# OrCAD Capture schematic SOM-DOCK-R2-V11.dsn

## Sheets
1 Title / Notes: title: SOMPLC-DOCKV1 R2; rev: 0.8; company: TI
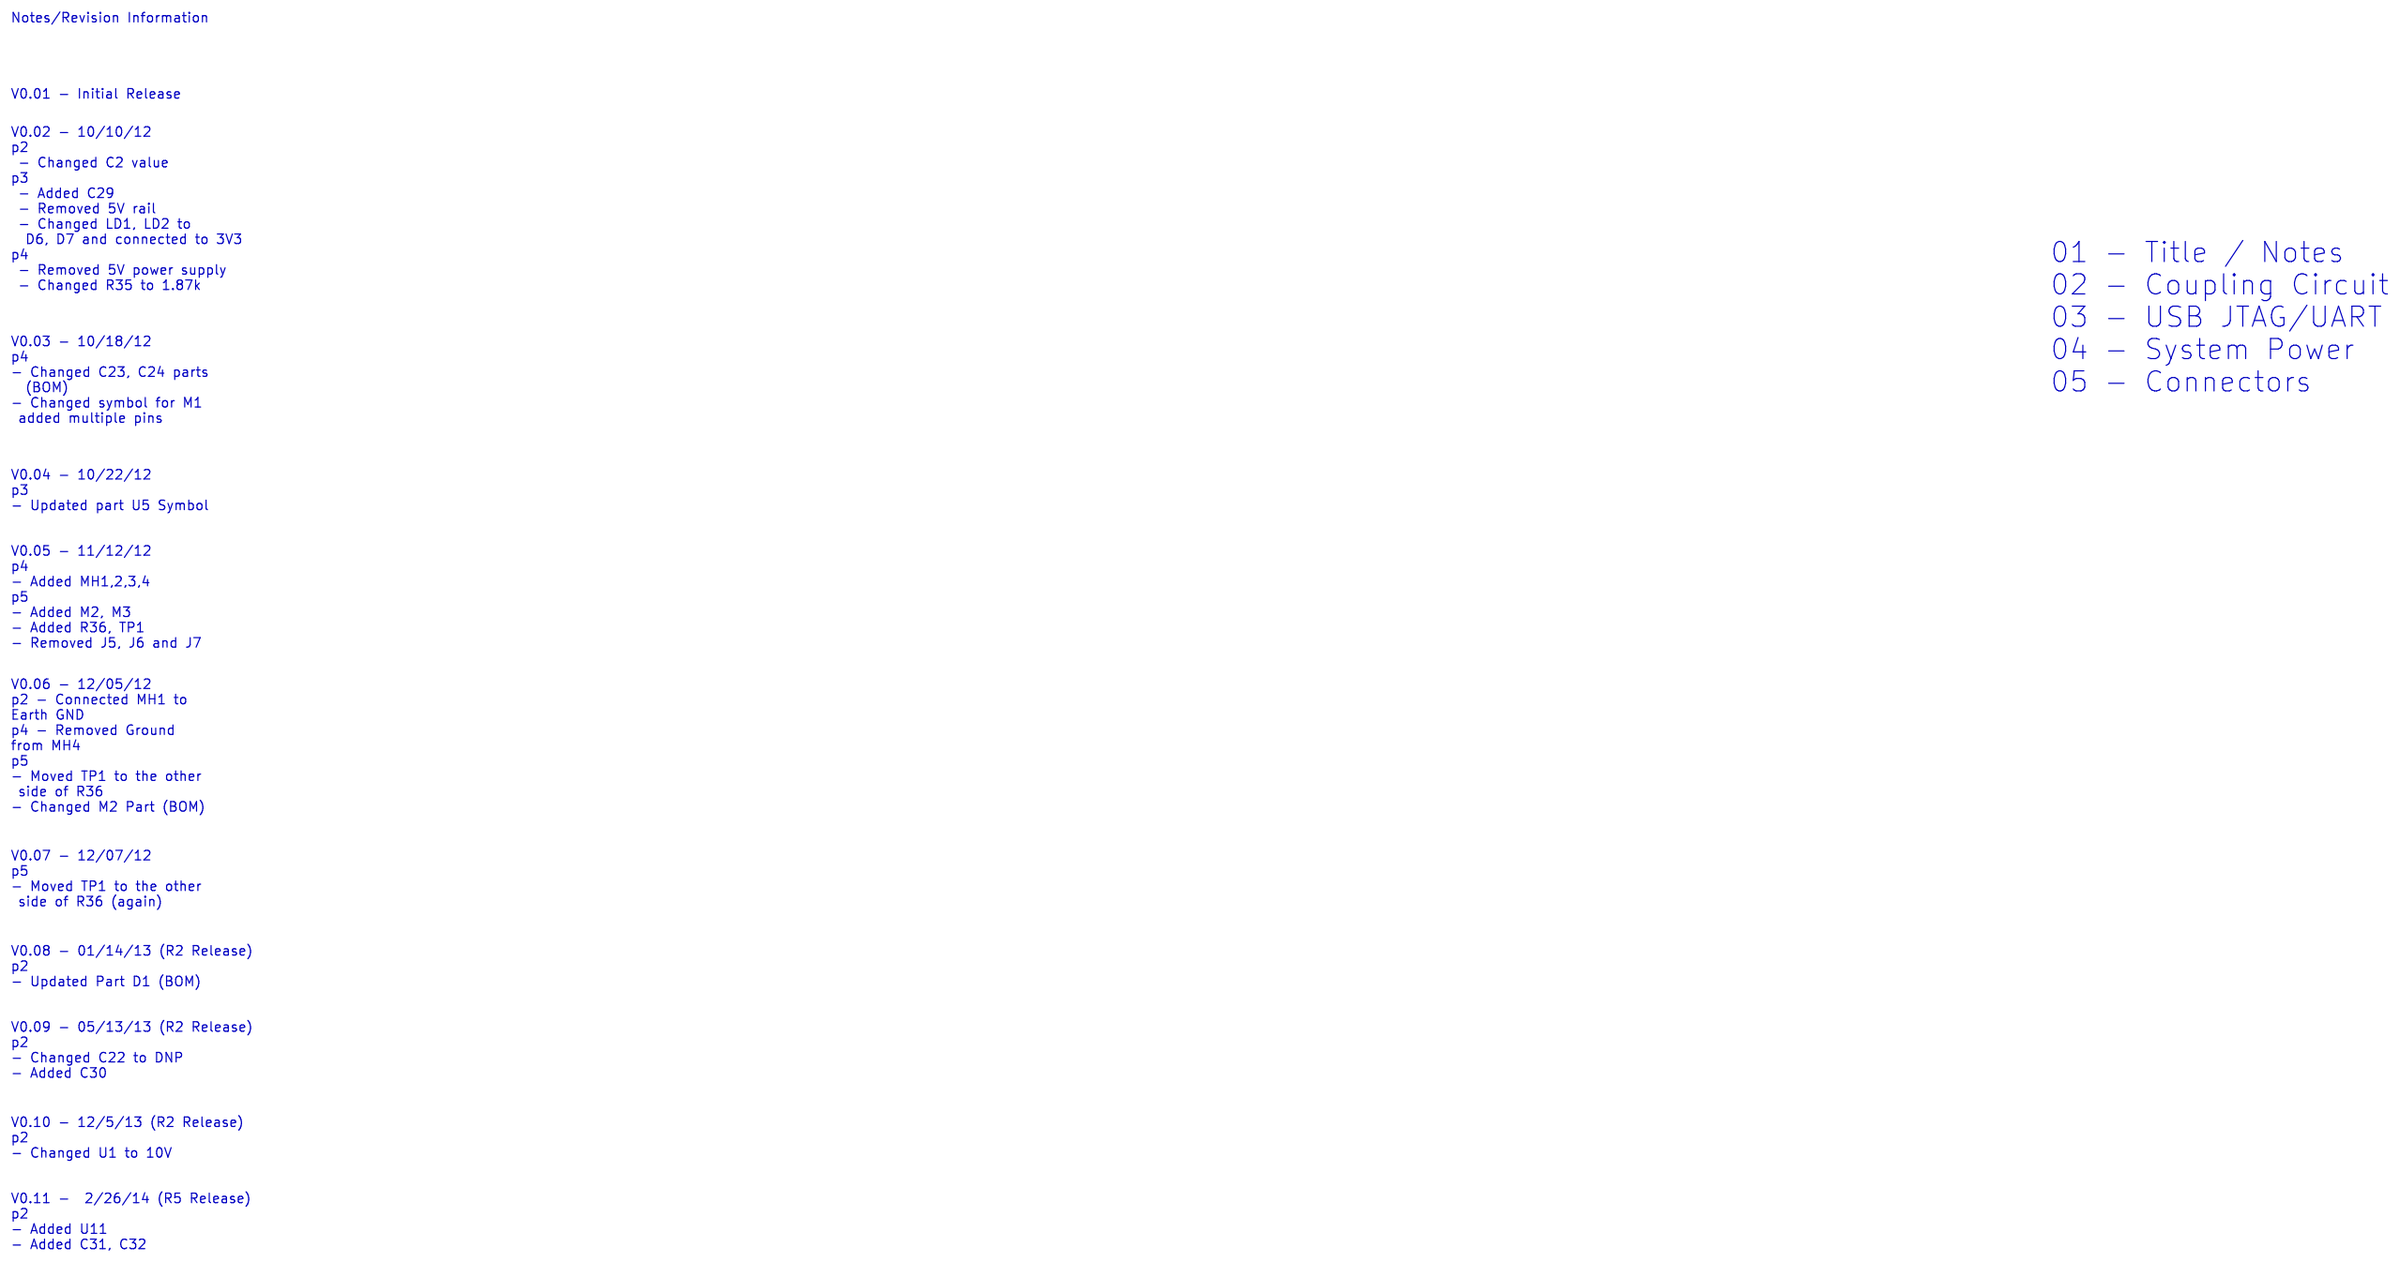
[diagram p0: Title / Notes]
2 Coupling Circuit: size B
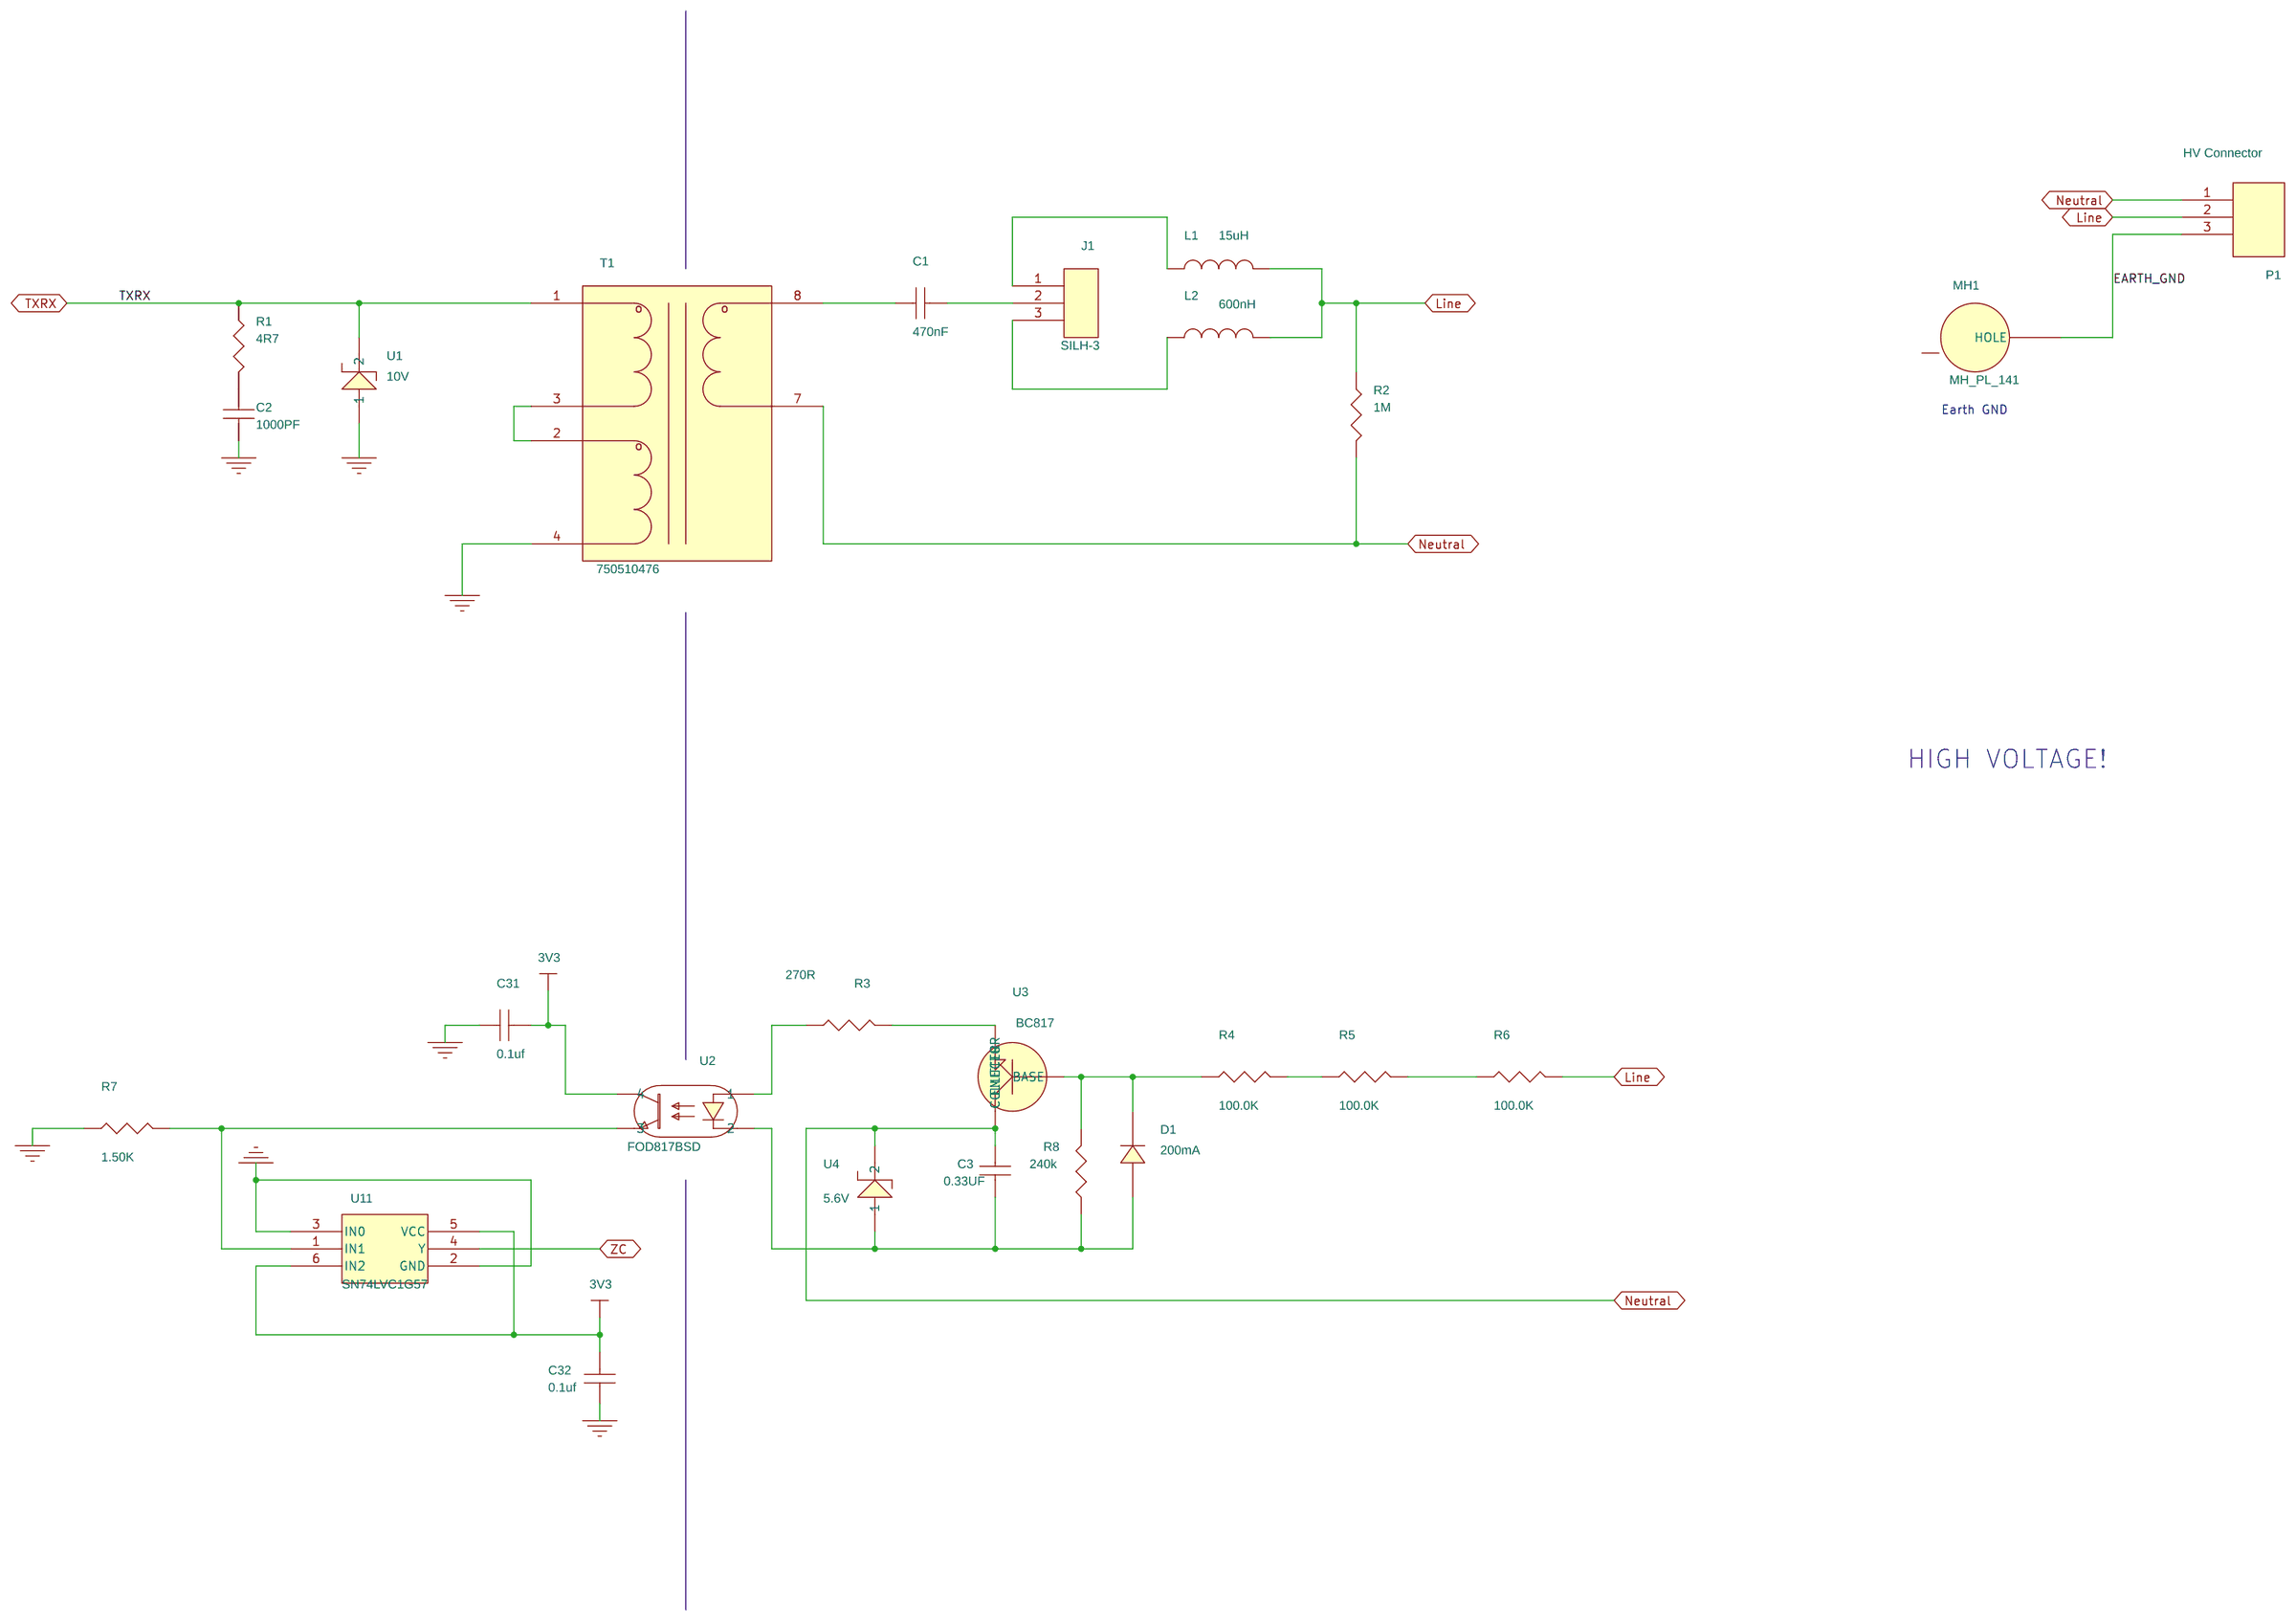
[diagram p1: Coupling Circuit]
3 USB JTAG/UART: size B
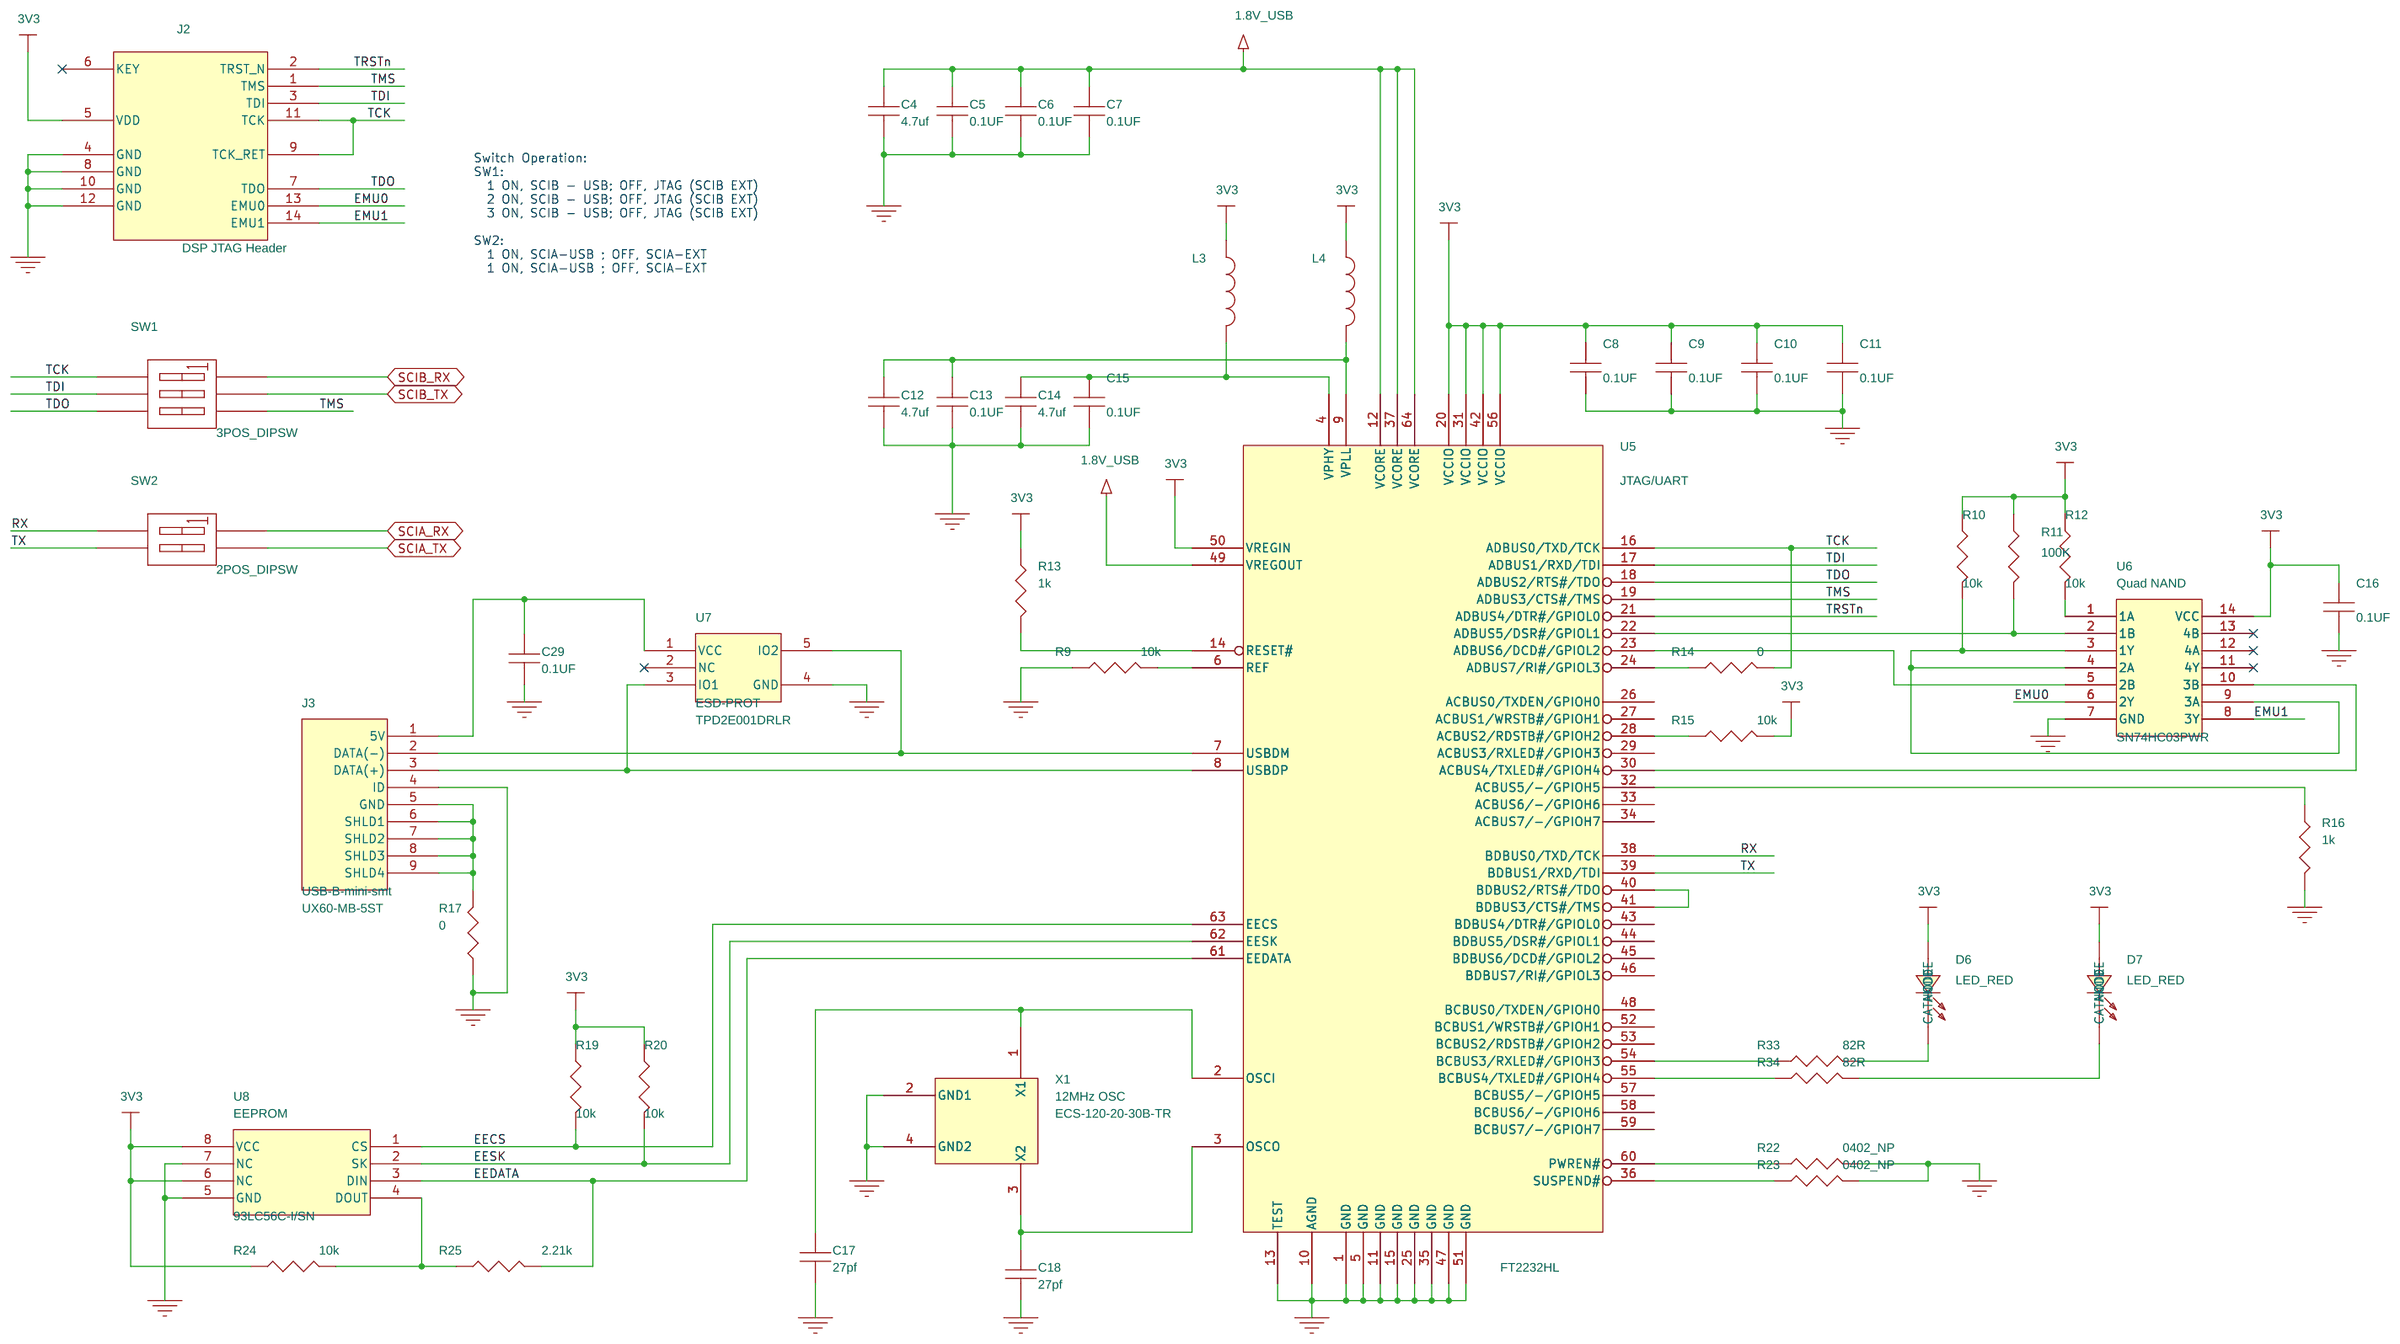
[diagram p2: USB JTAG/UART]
4 System Power: size B
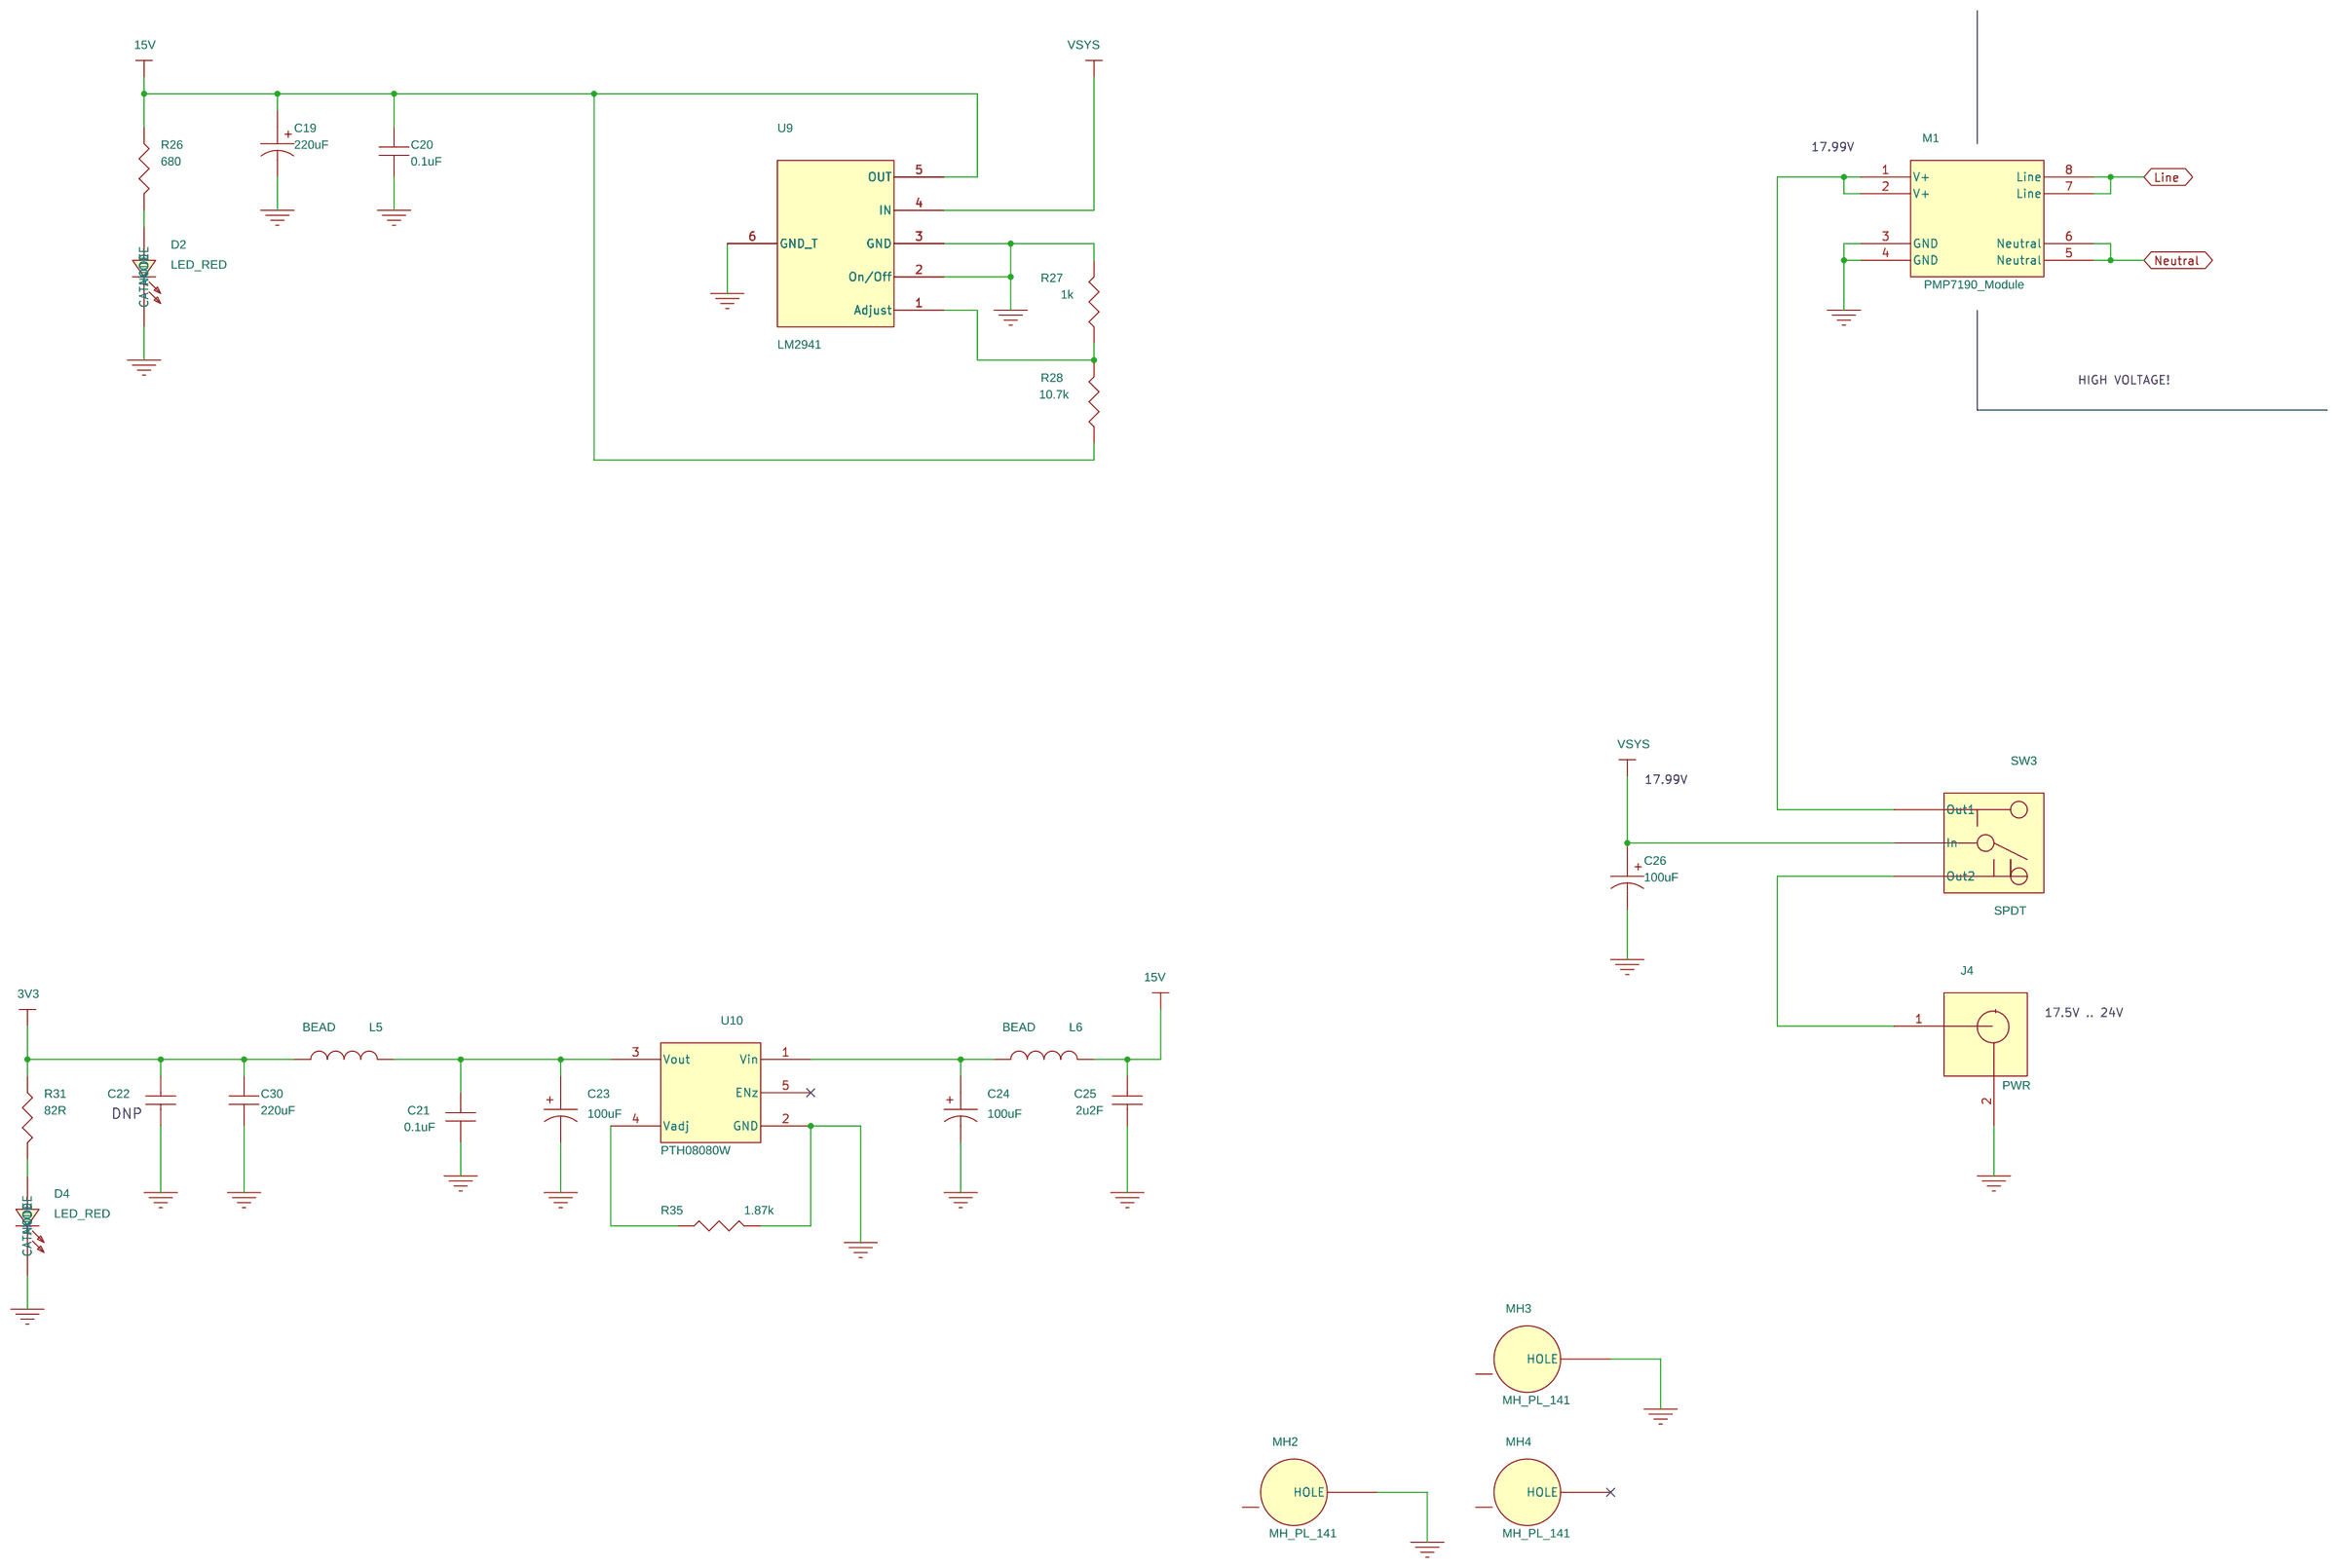
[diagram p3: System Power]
5 Connectors: size B
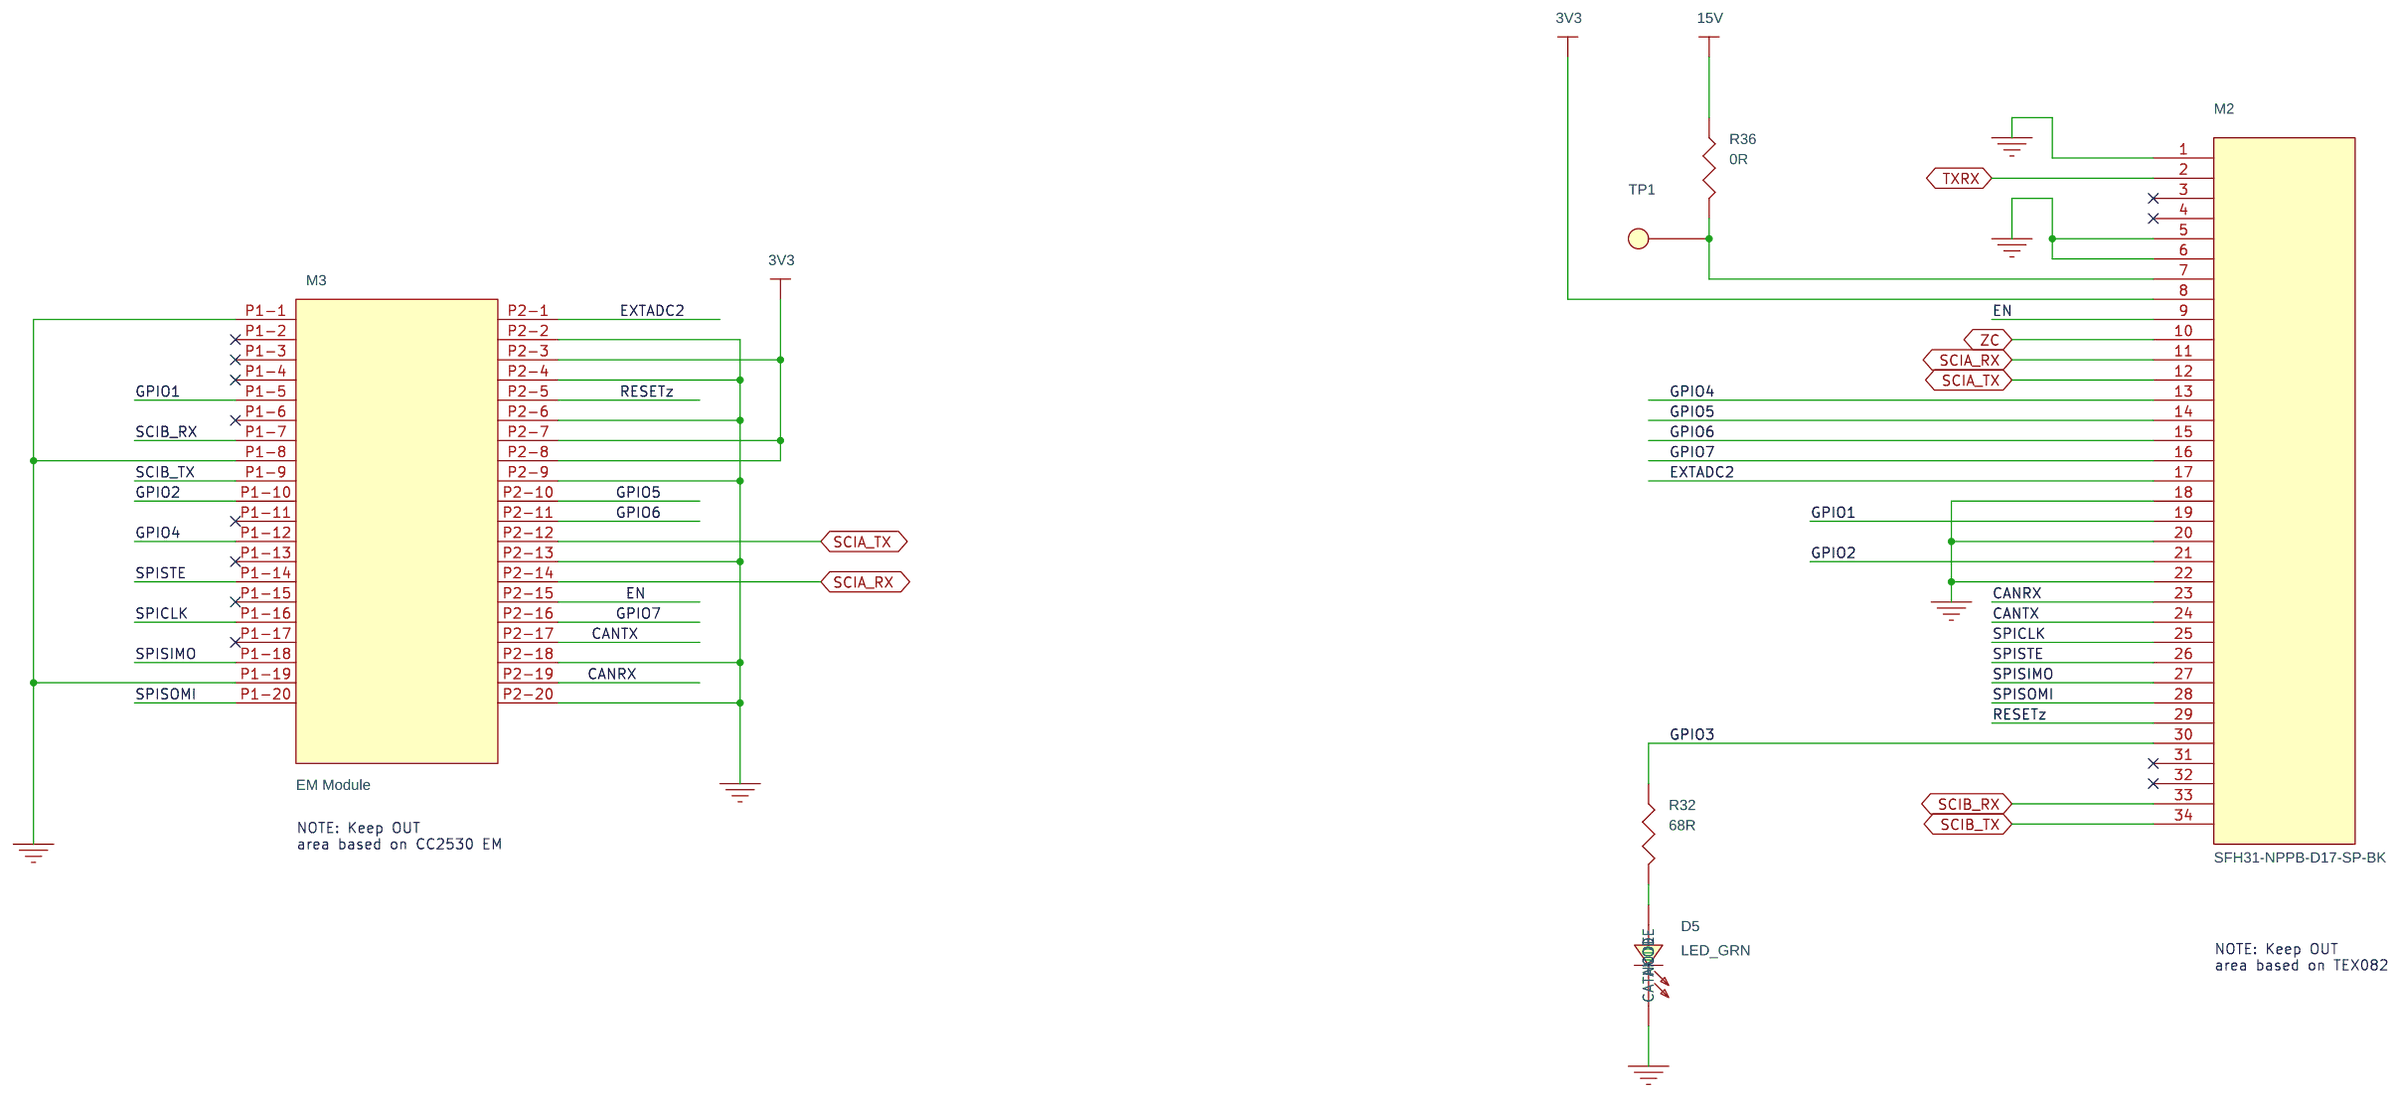
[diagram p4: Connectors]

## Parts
sheet Connectors
D5  LED_GRN  [LED0805]
M2  SFH31-NPPB-D17-SP-BK  [Female]
M3  EM Module  [Male]
R32  68R  [R0402]
R36  0R  [R0805]
TP1  TP_60  [TP_60]
sheet Coupling Circuit
C1  470nF  [Axial 0.591" (15.00mm) Spacing]
C2  1000PF  [C0603]
C3  0.33UF  [C0603]
C31  0.1uf  [C0805]
C32  0.1uf  [C0805]
D1  200mA  [LL-34]
J1  SILH-3  [HDR_1x3_100MILL_THRU_HOLE]
L1  15uH  [DR1040]
L2  600nH  [0.571" L x 0.492" W x 0.197" H]
MH1  MH_PL_141  [MH_141]
P1  HV Connector  [see datasheet]
R1  4R7  [R0805]
R2  1M  [R0805]
R3  270R  [R0805]
R4  100.0K  [R0805]
R5  100.0K  [R0805]
R6  100.0K  [R0805]
R7  1.50K  [R0805]
R8  240k  [R0805]
T1  750510476  [see datasheet]
U1  10V  [DO-214AA]
U2  FOD817BSD  [4-SMD]
U3  BC817  [SOT-23-3]
U4  5.6V  [LL-34]
U11  SN74LVC1G57  [SOT-23-6 (DVB)]
sheet System Power
C19  220uF  [Radial]
C20  0.1uF  [C0603]
C21  0.1uF  [C0603]
C22  2u2F  [C1210]
C23  100uF  [C2917P]
C24  100uF  [C2917P]
C25  2u2F  [C1210]
C26  100uF  [Radial]
C30  220uF  [C1210]
D2  LED_RED  [LED0805]
D4  LED_RED  [LED0805]
J4  PWR  [thru-hole]
L5  BEAD  [IND0402]
L6  BEAD  [IND0402]
M1  PMP7190_Module  [custom]
MH2  MH_PL_141  [MH_141]
MH3  MH_PL_141  [MH_141]
MH4  MH_PL_141  [MH_141]
R26  680  [R0402]
R27  1k  [R0402]
R28  10.7k  [R0402]
R31  82R  [R0402]
R35  1.87k  [R0402]
SW3  SPDT  [2 thru-hole]
U9  LM2941  [TO-263-5]
U10  PTH08080W  [PTH_5]
sheet USB JTAG/UART
C4  4.7uf  [C0402]
C5  0.1UF  [C0402]
C6  0.1UF  [C0402]
C7  0.1UF  [C0402]
C8  0.1UF  [C0402]
C9  0.1UF  [C0402]
C10  0.1UF  [C0402]
C11  0.1UF  [C0402]
C12  4.7uf  [C0402]
C13  0.1UF  [C0402]
C14  4.7uf  [C0402]
C15  0.1UF  [C0402]
C16  0.1UF  [C0402]
C17  27pf  [C0402]
C18  27pf  [C0402]
C29  0.1UF  [C0402]
D6  LED_RED  [LED0805]
D7  LED_RED  [LED0805]
J2  DSP JTAG Header  [hdr_14p]
J3  USB-B-mini-smt  [female?]
L3  HZ0805E601R-10  [805]
L4  HZ0805E601R-10  [805]
R9  10k  [R0402]
R10  10k  [R0402]
R11  100K  [R0603]
R12  10k  [R0402]
R13  1k  [R0402]
R14  0  [R0402]
R15  10k  [R0402]
R16  1k  [R0402]
R17  0  [R0402]
R19  10k  [R0402]
R20  10k  [R0402]
R22  0402_NP  [R0402]
R23  0402_NP  [R0402]
R24  10k  [R0402]
R25  2.21k  [R0402]
R33  82R  [R0402]
R34  82R  [R0402]
SW1  3POS_DIPSW  [3PDIPSW]
SW2  2POS_DIPSW  [2PDIPSW]
U5  JTAG/UART  [64-LQFP]
U6  Quad NAND  [14-TSSOP]
U7  ESD-PROT  [SOT-553]
U8  EEPROM  [8-SOIC]
X1  12MHz OSC  [4-SMD]

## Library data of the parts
D5 = LED: LED SMD 0805 - Green; Distributor: Digikey; Distributor Part Number: 404-1021-1; Part Number: 400-00001; Part Type: FET_DIODE; Vendor: Stanley; Vendor PN: PG1112H-TR; Voltage: 2.1V
M2 = SOM34PinConnector: CONN HDR FMAL 34PS 1.27MM SMD AU; Distributor: digikey; Distributor Part Number: S9117-ND; Part Number: 320-00014; Part Type: CONN; Vendor: Sullins Connector Solutions
M3 = EM_MODULE: 2x 20P SMT HDR; Distributor: mouser; Distributor Part Number: 649-87409-110LF; Part Number: 406-00002; Part Type: Module; Vendor: FCI; Vendor PN: 87409-110LF
R32 = RES_1: RES 68 OHM 1/10W 5% 0402 SMD; Distributor: digikey; Distributor Part Number: P68JCT-ND; Part Number: 310-00139; Part Type: RES; Vendor: panasonic; Vendor PN: ERJ-2GEJ680X
R36 = RES: RES 0.0 OHM 1/8W 0805 SMD; Distributor: digikey; Distributor Part Number: 311-0.0ARCT-ND; Part Number: 310-00113; Vendor: Yageo; Vendor PN: RC0805JR-070RL
TP1 = Test_Point: 60 mil round test point, SMT; Part Number: 280-00010; Part Type: MTG_HOLE_TP; Vendor: TI; Vendor PN: TI-TP-60mil
C1 = CAP: Part Number: 300-00047; Vendor: PANASONIC; Vendor PN: ECQ-E4474KF
C2 = CAP: Capacitor,1000PF,50 V,10 %,X7R,0603; Part Number: 100-00025; Tolerance: 0.1; Vendor: AVX; Vendor PN: 06035C102KAT*A; Voltage: 50V; Datasheet: http://www.avxcorp.com/docs/Catalogs/cx7r.pdf
C3 = CAP: Part Number: 100-00126; Vendor: Murata; Vendor PN: GRM188R71C334KA01D
C31 C32 = CAP: CAP CER 0.1UF 25V 10% X7R 0805; Distributor: digikey; Distributor Part Number: 399-1168-1-ND; Part Number: 300-00131; Vendor: Kemet; Vendor PN: C0805C104K3RACTU; Voltage: 25V
D1 = DIODE_SMC: DIODE STANDARD 200mA LL-34; Distributor: Digikey; Distributor Part Number: 568-1749-1-ND; FPLIST: LL-34, LLDS, SOD80C; Part Number: 400-00010; Part Type: FET_DIODE; Vendor: NXP Semi; Vendor PN: PMLL4148L,115
J1 = CONN_1x3_100mill_STD: 3 pin 100mill standard header; Part Number: 320-00008; Part Type: CONN
L1 = INDUCTOR_AIR_CORE: INDUCTOR POWER SHIELD 15UH SMD; Distributor: Digikey; Distributor Part Number: 513-1400-1-ND; Part Number: 330-00027; Part Type: MAGNETICS; Vendor: Coiltronics/Cooper; Vendor PN: DR1040-150-R
L2 = INDUCTOR_AIR_CORE_1: COIL POWER CHOKE 600nH 27A SMD; Distributor: Digikey; Distributor Part Number: PCD2022CT-ND; Part Number: 330-00020; Part Type: MAGNETICS; Vendor: Panasonic - ECG; Vendor PN: ETQ-P5LR60XFA
MH1-MH4 = MOUNTING_HOLE_PLATE: MTG_HOLE,0.141 hole, 0.25 pad, plated; Part Number: 480-00002; Part Type: MTG_HOLE_TP; Vendor: TI; Vendor PN: 280-00002
P1 = HDR_1X3: TERM BLOCK 3POS SIDE ENT 5.08MM; Distributor: digikey; Distributor Part Number: A98343-ND; Part Number: 320-00036; Part Type: CONN; Vendor: TE Connectivity; Vendor PN: 282841-3
R1 = RES_3: Part Number: 310-00075; Part Type: RES; Vendor: Panasonic; Vendor PN: ERJ-6GEYJ4R7V
R2 = RES_7: Part Number: 110-00031; Part Type: RES; Vendor: AVX; Vendor PN: CR21-105J-*
R3 = RES_4: Part Number: 110-00238; Part Type: RES; Vendor: Rohm; Vendor PN: MCR10EZPJ271
R4 = RES_6: RESISTOR,100.0K,0.125 W,1 %,0805; Part Number: 110-00018; Part Type: RES; Tolerance: 0.01; Vendor: AVX; Vendor PN: CR21-1003F-*; Voltage: 0.125W; Datasheet: http://www.avxcorp.com/docs/Catalogs/cr-cj.pdf
R5 = RES: RESISTOR,100.0K,0.125 W,1 %,0805; Part Number: 110-00018; Tolerance: 0.01; Vendor: AVX; Vendor PN: CR21-1003F-*; Voltage: 0.125W; Datasheet: http://www.avxcorp.com/docs/Catalogs/cr-cj.pdf
R6 = RES_5: RESISTOR,100.0K,0.125 W,1 %,0805; Part Number: 110-00018; Part Type: RES; Tolerance: 0.01; Vendor: AVX; Vendor PN: CR21-1003F-*; Voltage: 0.125W; Datasheet: http://www.avxcorp.com/docs/Catalogs/cr-cj.pdf
R7 = RES_1: Part Number: 110-00048; Part Type: RES; Vendor: AVX; Vendor PN: CR21-1501F-*
R8 = RES_2: Part Number: 110-00239; Part Type: RES; Vendor: Rohm; Vendor PN: MCR10EZPF2403
T1 = XFMR_PLC_2: Transformer PLC; Part Number: 330-00033; Part Type: MAGNETICS; Vendor: WURTH ELEKTRONIK
U1 = Diode_Zener: TRANSIL 600W 10V BIDIR SMB; Distributor: digikey; Distributor Part Number: 497-7427-2-ND; Part Number: 400-00014; Part Type: FET_DIODE; Vendor: STMicroelectronics; Vendor PN: SM6T10CA
U2 = OPTO2: Optoisolator, 5000Vrms, 70V; Distributor: Mouser; Distributor Part Number: 512-FOD817BSD; Part Number: 402-00069; Part Type: IC; Vendor: Fairchild Opto
U3 = NPN2: BJT, NPN, Ic=500mA, SOT-23-3; Distributor: Digikey; Distributor Part Number: BC817-40LT1GOSCT-ND; Part Number: 402-00070; Part Type: IC; Vendor: On Semi; Vendor PN: BC817-40LT1G
U4 = Diode_Zener_1: DIODE ZENER 500mW 5.6V LL-34; Distributor: Digikey; Distributor Part Number: 568-3797-1-ND; FPLIST: LL-34, LLDS, SOD80C; Part Number: 400-00009; Part Type: FET_DIODE; Vendor: NXP Semi; Vendor PN: BZV55-C5V6,115
U11 = SN74LVC1G5: CONFIGURABLE MULTIPLE-FUNCTION GATE; Distributor: digikey; Distributor Part Number: 296-15574-1-ND; Part Number: 402-00056; Part Type: IC; Vendor: TI; Vendor PN: SN74LVC1G57DBVR; Datasheet: www.ti.com
C19 = CAP_POL: CAP ALUM 220UF 35V 20% SMD; Distributor: digikey; Distributor Part Number: PCE3955CT-ND; FPLIST: Radial, Can - SMD 0.315" DIA; Part Number: 300-00115; Part Type: CAP; Vendor: PANASONIC; Vendor PN: EEE-1VA221UP; Voltage: 35V
C20 C21 = CAP: CAP CER 0.1UF (100nF) 50V Y5V 0603; Distributor: digikey; Distributor Part Number: 445-1324-2-ND; Part Number: 300-00113; Vendor: TDK; Vendor PN: C1608Y5V1H104Z; Voltage: 50V
C22 C25 = CAP: CAP CER 2.2UF 25V 10% X7R 1210; Distributor: digikey; Distributor Part Number: 399-3084-1-ND; Part Number: 300-00116; Vendor: kemet; Vendor PN: C1210C225K3RACTU; Voltage: 25V
C23 C24 = CAP_POL: CAP TANT 100UF 20V 10% 2917; Distributor: digikey; Distributor Part Number: 718-1744-1-ND; Part Number: 300-00117; Part Type: CAP; Vendor: Vishay; Vendor PN: 293D107X9020D2TE3; Voltage: 20V
C26 = CAP_POL: CAP ALUM 100UF 35V 20% SMD; Distributor: digikey; Distributor Part Number: PCE3951CT-ND; FPLIST: Radial, Can - SMD 0.248" DIA; Part Number: 300-00114; Part Type: CAP; Vendor: PANASONIC; Vendor PN: EEE-1VA101XP; Voltage: 35V
C30 = CAP: Tantalum Capacitors - Solid SMD 220uF 10v 20% Tol ESR = 1300; Distributor: mouser; Distributor Part Number: 581-TLNT227M010R1300; Part Number: 300-00123; Vendor: AVX; Vendor PN: TLNT227M010R1300; Voltage: 10V
D2 D4 D6 D7 = LED: LEDs SMD 0805 - Red; Distributor: Digikey; Distributor Part Number: 404-1017-1; Part Number: 400-00002; Part Type: FET_DIODE; Vendor: Stanley; Vendor PN: BR1112H-TR; Voltage: 2.1V
J4 = CONN_PWR_BARREL: CON PWR JCK 2.0 X 6.5MM W/O SW; Distributor: digikey; Distributor Part Number: CP-037A-ND; Part Number: 320-00039; Part Type: CONN; Vendor: CUI; Vendor PN: PJ-037A
L5 = INDUCTOR_AIR_CORE_1: FERRITE CHIP 70 OHM 0402; Distributor: digikey; Distributor Part Number: 490-5438-2-ND; Part Number: 330-00041; Part Type: MAGNETICS; Vendor: MURATA; Vendor PN: BLM15AX700SN1D
L6 = INDUCTOR_AIR_CORE: FERRITE CHIP 70 OHM 0402; Distributor: digikey; Distributor Part Number: 490-5438-2-ND; Part Number: 330-00041; Part Type: MAGNETICS; Vendor: MURATA; Vendor PN: BLM15AX700SN1D
M1 = PMP7190_Module: PMP7190 custom module AC/DC; Part Number: 403-00013; Part Type: POWER; Vendor PN: PMP7190
R26 = RES_2: RES 680 OHM 1/16W 5% 0402 SMD; Distributor: digikey; Distributor Part Number: RHM680JCT-ND; Part Number: 310-00103; Part Type: RES; Vendor: Rohm Semiconductor; Vendor PN: MCR01MZPJ681
R27 = RES_1: RES 1.00K OHM 1/10W 1% 0402 SMD; Distributor: digikey; Distributor Part Number: P1.00KLCT-ND; Part Number: 310-00080; Part Type: RES; Vendor: Panasonic; Vendor PN: ERJ-2RKF1001X
R28 = RES: RES 10.7K OHM 1/10W 1% 0402 SMD; Distributor: digikey; Distributor Part Number: P10.7KLCT-ND; Part Number: 310-00138; Vendor: panasonic; Vendor PN: ERJ-2RKF1072X
R31 = RES_3: RES 82 OHM 0402; Part Number: 310-00115; Part Type: RES
R35 = RES_4: RES 1.87K OHM 1/10W 1% 0402 SMD; Distributor: digikey; Distributor Part Number: P1.87KLCT-ND; Part Number: 310-00140; Part Type: RES; Vendor: panasonic; Vendor PN: ERJ-2RKF1871X
SW3 = Switch_SPDT: toggle switch SPDT; Distributor: mouser; Distributor Part Number: 108-2AS1T1203-EVX; Part Number: 206-00015; Part Type: SWITCH; Vendor: Mountain Switch; Vendor PN: 108-2AS1T1203-EVX
U9 = LM2941_TO263_5: IC REG LDO ADJ 1A TO-263-5; Distributor: Digikey; Distributor Part Number: LM2941SXCT-ND; Part Number: 402-00072; Part Type: IC; Vendor: National Semiconductor; Vendor PN: LM2941SX/NOPB
U10 = POLA_MODULE_5PIN: MODULE PIP .9-5.5V 2.25A SMD; Distributor: digikey; Distributor Part Number: 296-19803-ND; Part Number: 403-00012; Part Type: POWER; Vendor: TI; Vendor PN: PTH08080WAS
C4 C12 C14 = CAP: CAP CER 4.7UF 6.3V X5R 0402; Distributor: digikey; Distributor Part Number: 490-5408-2-ND; Part Number: 300-00073; Vendor: MURATA; Vendor PN: GRM155R60J475ME87D; Voltage: 6.3V
C5-C11 C13 C15 C16 C29 = CAP: Capacitor,0.1UF, X7R, 16 V, 0402, 10%; Part Number: 100-00108; Tolerance: 0.1; Vendor: KEMET; Vendor PN: C0402C104K4RACTU; Voltage: 16V; Datasheet: http://www.kemet.com/kemet/web/homepage/kechome.nsf/vapubfiles/F3102X7R.pdf/$file/F3102X7R.pdf
C17 C18 = CAP: CAP CERAMIC 27PF 50V NP0 0402; Distributor: digikey; Distributor Part Number: 399-1016-2-ND; Part Number: 300-00074; Vendor: Kemet; Vendor PN: C0402C270J5GACTU; Voltage: 50V
J2 = CONN_DSP_JTAG: CONN. 2X7 HEADER, SMT, DSP JTAG, Pin 6 removed; Part Number: 120-00068; Part Type: CONN; Vendor: SAMTEC; Vendor PN: TSM-107-01-S-DV
J3 = USB-B-mini-smt: CONN RECEPT MINI USB2.0 5POS; Distributor: digikey; Distributor Part Number: H2959TR-ND; Part Number: 320-00004; Part Type: CONN; Vendor: Hirose Electric Co Ltd; Vendor PN: UX60-MB-5ST; Datasheet: http://www.hirose.co.jp/cataloge_hp/e24000019.pdf
L3 L4 = IND_1008LS: FERRITE 500MA 600 OHM 0805 SMD; Distributor: Digikey; Distributor Part Number: 240-2399-2-ND; Part Number: 330-00025; Part Type: MAGNETICS; Vendor: Laird-Signal Integrity Products; Voltage: 500mA
R9 = RES_15: RES 10K OHM 1/10W 5% 0402 SMD; Distributor: digikey; Distributor Part Number: P10KJTR-ND; Part Number: 310-00104; Part Type: RES; Vendor: Panasonic; Vendor PN: ERJ-2GEJ103X
R10 = RES_5: RES 10K OHM 1/10W 5% 0402 SMD; Distributor: digikey; Distributor Part Number: P10KJTR-ND; Part Number: 310-00104; Part Type: RES; Vendor: Panasonic; Vendor PN: ERJ-2GEJ103X
R11 = RES_14: RESISTOR,100K, 0.1W, 5%, 0603; Distributor: Digikey; Distributor Part Number: P100KGTR-ND; Part Number: 110-00179; Part Type: RES; Tolerance: 0.05; Vendor: Panasonic; Vendor PN: ERJ-3GEYJ104V; Voltage: 0.1W; Datasheet: http://www.panasonic.com/industrial/components/pdf/AOA0000CE1.pdf
R12 = RES_1: RES 10K OHM 1/10W 5% 0402 SMD; Distributor: digikey; Distributor Part Number: P10KJTR-ND; Part Number: 310-00104; Part Type: RES; Vendor: Panasonic; Vendor PN: ERJ-2GEJ103X
R13 = RES_6: RES 1.00K OHM 1/10W 1% 0402 SMD; Distributor: digikey; Distributor Part Number: P1.00KLCT-ND; Part Number: 310-00080; Part Type: RES; Vendor: Panasonic; Vendor PN: ERJ-2RKF1001X
R14 = RES_3: RES 0.0 OHM 1/10W 0402 SMD; Distributor: digikey; Distributor Part Number: P0.0JCT-ND; Part Number: 310-00102; Part Type: RES; Vendor: Panasonic - ECG; Vendor PN: ERJ-2GE0R00X
R15 = RES_9: RES 10K OHM 1/10W 5% 0402 SMD; Distributor: digikey; Distributor Part Number: P10KJTR-ND; Part Number: 310-00104; Part Type: RES; Vendor: Panasonic; Vendor PN: ERJ-2GEJ103X
R16 = RES_11: RES 1.00K OHM 1/10W 1% 0402 SMD; Distributor: digikey; Distributor Part Number: P1.00KLCT-ND; Part Number: 310-00080; Part Type: RES; Vendor: Panasonic; Vendor PN: ERJ-2RKF1001X
R17 = RES_8: RES 0.0 OHM 1/10W 0402 SMD; Distributor: digikey; Distributor Part Number: P0.0JCT-ND; Part Number: 310-00102; Part Type: RES; Vendor: Panasonic - ECG; Vendor PN: ERJ-2GE0R00X
R19 = RES_7: RES 10K OHM 1/10W 5% 0402 SMD; Distributor: digikey; Distributor Part Number: P10KJTR-ND; Part Number: 310-00104; Part Type: RES; Vendor: Panasonic; Vendor PN: ERJ-2GEJ103X
R20 = RES_16: RES 10K OHM 1/10W 5% 0402 SMD; Distributor: digikey; Distributor Part Number: P10KJTR-ND; Part Number: 310-00104; Part Type: RES; Vendor: Panasonic; Vendor PN: ERJ-2GEJ103X
R22 = RES: NO POP
R23 = RES_12: NO POP; Part Type: RES
R24 = RES_2: RES 10K OHM 1/10W 5% 0402 SMD; Distributor: digikey; Distributor Part Number: P10KJTR-ND; Part Number: 310-00104; Part Type: RES; Vendor: Panasonic; Vendor PN: ERJ-2GEJ103X
R25 = RES_10: RES 2.21K OHM 1/10W 1% 0402 SMD; Distributor: digikey; Distributor Part Number: P2.21KLCT-ND; Part Number: 310-00100; Part Type: RES; Vendor: Panasonic - ECG; Vendor PN: ERJ-2RKF2211X
R33 = RES_4: RES 82 OHM 0402; Part Number: 310-00115; Part Type: RES
R34 = RES_13: RES 82 OHM 0402; Part Number: 310-00115; Part Type: RES
SW1 = SWITCH_DIP_SMT3: SWITCH DIP TOP SLIDE 3POS SMD; Distributor: Digikey; Part Number: 206-00013; Part Type: SWITCH; Vendor: C&K COMPONENTS; Vendor PN: SDA03H1SBD
SW2 = SWITCH_DIP_SMT2: SWITCH DIP TOP SLIDE 2POS SMD; Distributor: Digikey; Distributor Part Number: CKN6056-ND; Part Number: 206-00014; Part Type: SWITCH; Vendor: C&K COMPONENTS; Vendor PN: SDA02H1SBD
U5 = FT2232H: IC USB HS DUAL UART/FIFO 64-LQFP; Distributor: digikey; Distributor Part Number: 768-1024-2-ND; Part Number: 402-00045; Part Type: IC; Pin Numbers Visible: <Pin Numbers Visible>; Vendor: FTDI; Vendor PN: FT2232HL
U6 = SN74HC: IC GATE POS-NAND QD 2IN 14-TSSOP; Distributor: digikey; Distributor Part Number: SN74HC03PWR-ND; Part Number: 402-00043; Part Type: IC; Vendor: TI; Vendor PN: SN74HC03PWR
U7 = TPD2E001: IC ESD-PROT ARRAY 2CH SOT-5; Distributor: digikey; Distributor Part Number: 296-21883-2-ND; Part Number: 402-00047; Part Type: IC; Vendor: TI; Vendor PN: TPD2E001DRLR
U8 = 93LC56C: IC EEPROM 2KBIT 3MHZ 8SOIC; Distributor: digikey; Distributor Part Number: 93LC56C-I/SN-ND; Part Number: 402-00046; Part Type: IC; Vendor: micro chip; Vendor PN: 93LC56C-I/SN
X1 = Crystal_4pin_SMT: CRYSTAL 12.000 MHZ 20PF SMD; Distributor: Digikey; Distributor Part Number: XC1118TR-ND; FPLIST: 4-SMD, No Lead (DFN, LCC); Part Number: 405-00013; Part Type: OSC_XTAL; Vendor: ECS; Vendor PN: ECS-120-20-30B-TR

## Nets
1.8V_USB: C4.1 C5.1 C6.1 C7.1 U5.12(VCORE) U5.37(VCORE) U5.49(VREGOUT) U5.64(VCORE)
3V3: C8.1 C9.1 C10.1 C11.1 C16.1 C22.1 C30.1 C31.2 C32.2 D6.1(ANODE) D7.1(ANODE) J2.5(VDD) L3.1 L4.1 L5.2 M2.8 M3.P2-3 M3.P2-7 M3.P2-8 R10.1 R11.1 R12.1 R13.1 R15.2 R19.1 R20.1 R24.1 R31.1 U2.4 U5.20(VCCIO) U5.31(VCCIO) U5.42(VCCIO) U5.50(VREGIN) U5.56(VCCIO) U6.14(VCC) U8.6(NC) U8.8(VCC) U11.5(VCC) U11.6(IN2)
15V: C19.1 C20.1 C25.1 L6.1 R26.1 R28.2 R36.1 U9.5(OUT)
GND: C2.2 C4.2 C5.2 C6.2 C7.2 C8.2 C9.2 C10.2 C11.2 C12.2 C13.2 C14.2 C15.2 C16.2 C17.2 C18.2 C19.2 C20.2 C21.2 C22.2 C23.2 C24.2 C25.2 C26.2 C29.2 C30.2 C31.1 C32.1 D2.2(CATHODE) D4.2(CATHODE) D5.2(CATHODE) J2.4(GND) J2.8(GND) J2.10(GND) J2.12(GND) J3.4(ID) J4.2 M1.3(GND) M1.4(GND) M2.1 M2.5 M2.6 M2.18 M2.20 M2.22 M3.P1-1 M3.P1-8 M3.P1-19 M3.P2-2 M3.P2-4 M3.P2-6 M3.P2-9 M3.P2-13 M3.P2-18 M3.P2-20 MH2.1(HOLE) MH3.1(HOLE) R7.2 R9.1 R16.2 R17.1 R22.2 R23.2 R27.1 R35.2 T1.4 U1.1 U5.1(GND) U5.5(GND) U5.10(AGND) U5.11(GND) U5.13(TEST) U5.15(GND) U5.25(GND) U5.35(GND) U5.47(GND) U5.51(GND) U6.7(GND) U7.4(GND) U8.5(GND) U8.7(NC) U9.2(On/Off) U9.3(GND) U9.6(GND_T) U10.2(GND) U11.2(GND) U11.3(IN0) X1.2(GND1) X1.4(GND2)
CANRX: M2.23 M3.P2-19
CANTX: M2.24 M3.P2-17
EARTH_GND: MH1.1(HOLE) P1.3
EECS: R19.2 U5.63(EECS) U8.1(CS)
EEDATA: R25.2 U5.61(EEDATA) U8.3(DIN)
EESK: R20.2 U5.62(EESK) U8.2(SK)
EMU0: J2.13(EMU0) U6.6(2Y)
EMU1: J2.14(EMU1) U6.8(3Y)
EN: M2.9 M3.P2-15
EXTADC2: M2.17 M3.P2-1
GPIO1: M2.19 M3.P1-5
GPIO2: M2.21 M3.P1-10
GPIO3: M2.30 R32.1
GPIO4: M2.13 M3.P1-12
GPIO5: M2.14 M3.P2-10
GPIO6: M2.15 M3.P2-11
GPIO7: M2.16 M3.P2-16
Line: L1.2 L2.2 M1.7(Line) M1.8(Line) P1.2 R2.1 R6.1
Neutral: C3.1 M1.5(Neutral) M1.6(Neutral) P1.1 R2.2 T1.7 U3.3(COLLECTOR) U4.2
RESETz: M2.29 M3.P2-5
RX: SW2.4 U5.38(BDBUS0/TXD/TCK)
SCIA_RX: M2.11 M3.P2-14 SW2.1
SCIA_TX: M2.12 M3.P2-12 SW2.2
SCIB_RX: M2.33 M3.P1-7 SW1.1
SCIB_TX: M2.34 M3.P1-9 SW1.2
SPICLK: M2.25 M3.P1-16
SPISIMO: M2.27 M3.P1-18
SPISOMI: M2.28 M3.P1-20
SPISTE: M2.26 M3.P1-14
TCK: J2.9(TCK_RET) J2.11(TCK) R14.2 SW1.6 U5.16(ADBUS0/TXD/TCK)
TDI: J2.3(TDI) SW1.5 U5.17(ADBUS1/RXD/TDI)
TDO: J2.7(TDO) SW1.4 U5.18(ADBUS2/RTS#/TDO)
TMS: J2.1(TMS) SW1.3 U5.19(ADBUS3/CTS#/TMS)
TRSTn: J2.2(TRST_N) U5.21(ADBUS4/DTR#/GPIOL0)
TX: SW2.3 U5.39(BDBUS1/RXD/TDI)
TXRX: M2.2 R1.1 T1.1 U1.2
Vsys: C26.1 SW3.2(In) U9.4(IN)
ZC: M2.10 U11.4(Y)
N17352575: C1.1 T1.8
N17352603: T1.2 T1.3
N17352620: C1.2 J1.2
N17352701: C3.2 D1.1(A) R8.2 U2.2 U4.1
N17352711: D1.2(K) R4.2 R8.1 U3.1(BASE)
N17352725: R3.1 U3.2(EMITTER)
N17352762: R3.2 U2.1
N17352809: R5.1 R6.2
N17352811: R4.1 R5.2
N17352822: R7.1 U2.3 U11.1(IN1)
N17370094: J1.1 L1.1
N17370103: J1.3 L2.1
N17371464: C17.1 U5.2(OSCI) X1.1(X1)
N17371472: C29.1 J3.1(5V) U7.1(VCC)
N17371494: C18.1 U5.3(OSCO) X1.3(X2)
N17371562: R24.2 R25.1 U8.4(DOUT)
N17371566: R9.2 U5.6(REF)
N17371576: C14.1 C15.1 L3.2 U5.4(VPHY)
N17371586: J3.5(GND) J3.6(SHLD1) J3.7(SHLD2) J3.8(SHLD3) J3.9(SHLD4) R17.2
N17371610: C12.1 C13.1 L4.2 U5.9(VPLL)
N17371675: R33.1 U5.54(BCBUS3/RXLED#/GPIOH3)
N17371691: R10.2 U6.3(1Y) U6.4(2A) U6.9(3A)
N17371695: R34.1 U5.55(BCBUS4/TXLED#/GPIOH4)
N17371707: R15.1 U5.28(ACBUS2/RDSTB#/GPIOH2)
N17371717: U5.23(ADBUS6/DCD#/GPIOL2) U6.5(2B)
N17371737: U5.30(ACBUS4/TXLED#/GPIOH4) U6.10(3B)
N17371758: R12.2 U6.1(1A)
N17371787: R11.2 U5.22(ADBUS5/DSR#/GPIOL1) U6.2(1B)
N17371810: U5.40(BDBUS2/RTS#/TDO) U5.41(BDBUS3/CTS#/TMS)
N17371858: R14.1 U5.24(ADBUS7/RI#/GPIOL3)
N17371884: J3.3(DATA(+)) U5.8(USBDP) U7.3(IO1)
N17371886: R22.1 U5.60(PWREN#)
N17371922: D6.2(CATHODE) R33.2
N17371924: R23.1 U5.36(SUSPEND#)
N17371926: R16.1 U5.32(ACBUS5/-/GPIOH5)
N17372081: D7.2(CATHODE) R34.2
N17372087: R13.2 U5.14(RESET#)
N17372147: J3.2(DATA(-)) U5.7(USBDM) U7.5(IO2)
N17388962: J4.1 SW3.3(Out2)
N17388974: M1.1(V+) M1.2(V+) SW3.1(Out1)
N17389435: R27.2 R28.1 U9.1(Adjust)
N17391019: C21.1 C23.1 L5.1 U10.3(Vout)
N17391029: C24.1 L6.2 U10.1(Vin)
N17391108: R35.1 U10.4(Vadj)
N17394692: M2.7 R36.2 TP1.1(TP1)
N17402884: D5.1(ANODE) R32.2
N17402945: D4.1(ANODE) R31.2
N17402948: D2.1(ANODE) R26.2
N17445287: C2.1 R1.2

Not connected (* = marked no-connect by the designer): J2 6(KEY)*; M2 3* 4* 31* 32*; M3 P1-2* P1-3* P1-4* P1-6* P1-11* P1-13* P1-15* P1-17*; MH4 1(HOLE)*; U5 26(ACBUS0/TXDEN/GPIOH0) 27(ACBUS1/WRSTB#/GPIOH1) 29(ACBUS3/RXLED#/GPIOH3) 33(ACBUS6/-/GPIOH6) 34(ACBUS7/-/GPIOH7) 43(BDBUS4/DTR#/GPIOL0) 44(BDBUS5/DSR#/GPIOL1) 45(BDBUS6/DCD#/GPIOL2) 46(BDBUS7/RI#/GPIOL3) 48(BCBUS0/TXDEN/GPIOH0) 52(BCBUS1/WRSTB#/GPIOH1) 53(BCBUS2/RDSTB#/GPIOH2) 57(BCBUS5/-/GPIOH5) 58(BCBUS6/-/GPIOH6) 59(BCBUS7/-/GPIOH7); U6 11(4Y)* 12(4A)* 13(4B)*; U7 2(NC)*; U10 5(ENz)*

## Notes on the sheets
sheet 1
- Notes/Revision Information
- V0.01 - Initial Release
- V0.02 - 10/10/12
  p2
   - Changed C2 value
  p3
   - Added C29
   - Removed 5V rail
   - Changed LD1, LD2 to
    D6, D7 and connected to 3V3
  p4
   - Removed 5V power supply
   - Changed R35 to 1.87k
- 01 - Title / Notes
  02 - Coupling Circuit
  03 - USB JTAG/UART
  04 - System Power
  05 - Connectors
- V0.03 - 10/18/12
  p4
  - Changed C23, C24 parts
    (BOM)
  - Changed symbol for M1
   added multiple pins
- V0.04 - 10/22/12
  p3
  - Updated part U5 Symbol
- V0.05 - 11/12/12
  p4
  - Added MH1,2,3,4
  p5
  - Added M2, M3
  - Added R36, TP1
  - Removed J5, J6 and J7
- V0.06 - 12/05/12
  p2 - Connected MH1 to
  Earth GND
  p4 - Removed Ground
  from MH4
  p5
  - Moved TP1 to the other
   side of R36
  - Changed M2 Part (BOM)
- V0.07 - 12/07/12
  p5
  - Moved TP1 to the other
   side of R36 (again)
- V0.08 - 01/14/13 (R2 Release)
  p2
  - Updated Part D1 (BOM)
- V0.09 - 05/13/13 (R2 Release)
  p2
  - Changed C22 to DNP
  - Added C30
- V0.10 - 12/5/13 (R2 Release)
  p2
  - Changed U1 to 10V
- V0.11 -  2/26/14 (R5 Release)
  p2
  - Added U11
  - Added C31, C32
sheet 2
- Earth GND
- HIGH VOLTAGE!
sheet 3
- Switch Operation:
  SW1:
    1 ON, SCIB - USB; OFF, JTAG (SCIB EXT)
    2 ON, SCIB - USB; OFF, JTAG (SCIB EXT)
    3 ON, SCIB - USB; OFF, JTAG (SCIB EXT)
  SW2:
    1 ON, SCIA-USB ; OFF, SCIA-EXT
    1 ON, SCIA-USB ; OFF, SCIA-EXT
sheet 4
- 17.99V
- HIGH VOLTAGE!
- 17.99V
- 17.5V .. 24V
- DNP
sheet 5
- NOTE: Keep OUT
  area based on CC2530 EM
- NOTE: Keep OUT
  area based on TEX082
